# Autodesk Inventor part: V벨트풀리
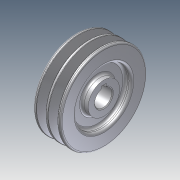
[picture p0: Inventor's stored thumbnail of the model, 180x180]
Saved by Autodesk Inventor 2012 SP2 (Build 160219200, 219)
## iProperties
Company: 한국ATC센터
Created: 2015-02
Part Number: V벨트풀리
Document SubType Name: Modeling
Designer: KYOUNG IL JANG
Density: 1 g/cm^3
Material: 기본값
Author: KYOUNG IL JANG
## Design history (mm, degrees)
sketch "스케치1"
  geometry: L1 (0, 0)-(35, 0); L2 (35, 0)-(35, 55); L3 (35, 55)-(31.062, 55); L4 (31.062, 55)-(27.001, 42.5); L5 (27.001, 42.5)-(22.999, 42.5); L6 (22.999, 42.5)-(18.938, 55); L7 (18.938, 55)-(16.062, 55); L8 (16.062, 55)-(12.001, 42.5); L9 (12.001, 42.5)-(7.999, 42.5); L10 (7.999, 42.5)-(3.938, 55); L11 (3.938, 55)-(0, 55); L12 (0, 55)-(0, 0); L13 (5.4, 50.5)-(14.6, 50.5); L14 (20.4, 50.5)-(29.6, 50.5); 3 further points
  constraints: 28 end point, 8 parallel, 6 collinear, 4 point on line, 3 midpoint, 2 perpendicular, 1 horizontal, 1 vertical alignment
  dimensions: "d0" = 36 deg angle of L8 L10; "d1" = 9.2 distance of L14.start L14.end; "d2" = 4.5 distance between parallel lines of L13 L11; "d3" = 8 distance between parallel lines of L9 L13; "d4" = 10 distance from line of point (25, 42.5) L2; "d5" = 15 distance of point (25, 42.5) point (10, 42.5); "d6" = 35 distance of L1.start L1.end; "d7" = 101 diameter of L14 L1
revolve "회전1" sketch "스케치1" stored, may be unused: angle "d8" = 90 deg
fillet "모깎기1" dims "d9" = 2
fillet "모깎기2" dims "d10" = 0.5
fillet "모깎기3" dims "d11" = 1
sketch "스케치2"
  geometry: L1 (0, 0)-(8, 0); L2 (8, 0)-(8, 20); L3 (8, 20)-(17, 20); L4 (17, 20)-(17, 35); L5 (17, 35)-(0, 35); L6 (0, 35)-(0, 0); L7 (35, 35)-(27, 35); L8 (27, 35)-(27, 20); L9 (27, 20)-(35, 20); L10 (35, 20)-(35, 35); L11 (35, 53)-(35, -53) reference
  constraints: 20 end point, 6 parallel, 3 collinear, 3 perpendicular, 1 horizontal
  dimensions: "d12" = 40 diameter of L9 L1; "d13" = 70 diameter of L7 L1; "d14" = 8 distance between parallel lines of L10 L8; "d15" = 10 distance between parallel lines of L8 L4; "d16" = 9 distance between parallel lines of L4 L2
revolve "회전2" sketch "스케치2" stored, may be unused: angle "d17" = 90 deg
hole "구멍1" diameter "d20" = 22; stored, may be unused: countersink angle "d24" = 90 deg, drill point angle "d26" = 118 deg; dims "d18" = 10, "d19" = 10, "d21" = 6, "d22" = 4, "d23" = 2, "d25" = 8
sketch "스케치3"
  geometry: L1 (-14.8, -3)-(-7.8, -3); L2 (-7.8, -3)-(-7.8, 3); L3 (-7.8, 3)-(-14.8, 3); L4 (-14.8, 3)-(-14.8, -3); C1 r 11 at (0, 0) reference; 2 further points
  constraints: 8 end point, 2 parallel, 1 horizontal, 1 horizontal alignment, 1 midpoint, 1 perpendicular
  dimensions: "d27" = 25.8 dimension on C1 L4; "d28" = 6 distance of L3.end L1.start; "d29" = 7 distance between parallel lines of L4 L2
extrude "돌출1" cut sketch "스케치3" stored distance "d30" = 10; taper "d31" = 0 deg
fillet "모깎기4" dims "d32" = 3
chamfer "모따기1" distance "d33" = 1; stored, may be unused: second distance "d34" = 2, angle "d35" = 45 deg
node "솔리드1"
